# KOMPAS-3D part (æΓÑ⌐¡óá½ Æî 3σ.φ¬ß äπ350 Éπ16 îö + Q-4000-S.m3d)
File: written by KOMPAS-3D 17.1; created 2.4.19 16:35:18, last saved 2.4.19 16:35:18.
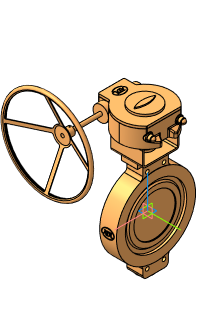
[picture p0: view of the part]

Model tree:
1. Операция без истории:1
